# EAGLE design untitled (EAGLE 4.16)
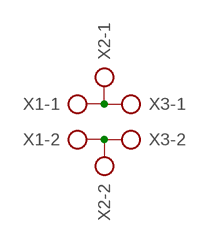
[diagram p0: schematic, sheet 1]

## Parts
X1  AK500/2  [AK500/2]
X2  AK500/2  [AK500/2]
X3  AK500/2  [AK500/2]

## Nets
N$17: X1.1 X2.1 X3.1
N$18: X1.2 X2.2 X3.2

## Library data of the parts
X1-X3 = con-ptr500:AK500/2: CONNECTOR

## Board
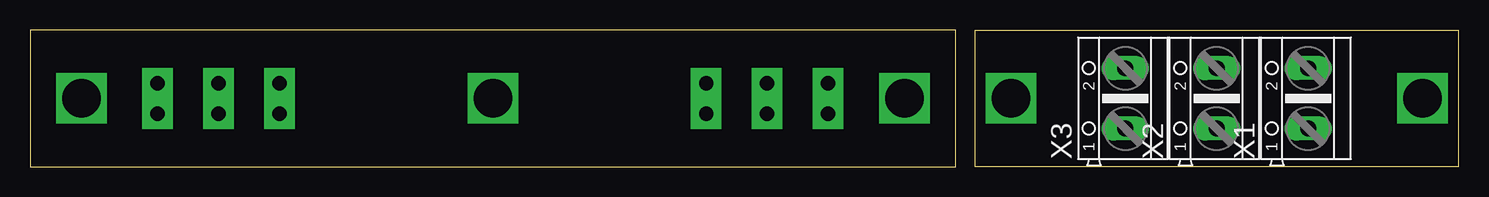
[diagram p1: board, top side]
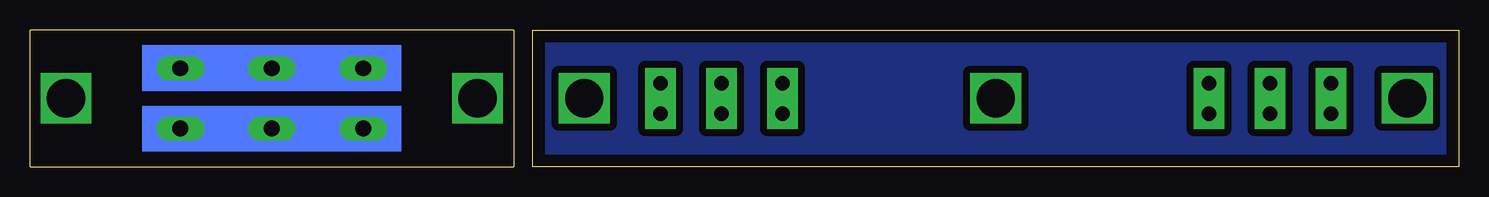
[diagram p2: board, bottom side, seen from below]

Size 119.05 x 11.44 mm. Coordinates in mm from the lower left corner, seen from the top.
Outline: 119.05,0.01 119.05,11.43
Outline: 78.74,11.43 78.74,0.01
Outline: 119.05,0 78.74,0
Outline: 78.74,11.44 119.05,11.44
Outline: 0,0.01 77.14,0.01 77.14,11.43 0,11.43 0,0.01
Copper layers (1*16): Top 0.035mm / dielectric 1.5mm / Bottom 0.035mm
Design rules "default": minimum track width 10mil, minimum drill 24mil, track to track 8mil, track to pad 8mil, pad to pad 8mil, via to via 8mil, smd to smd 8mil, copper to edge 40mil, drill to drill 8mil, minimum pad ring 10mil, minimum via ring 8mil, stop-mask expansion 4mil, vias tented up to drill 0mil, thermal gap 10mil

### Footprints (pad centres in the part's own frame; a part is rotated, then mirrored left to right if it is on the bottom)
AK500/2 = drill 1.321 long: 1 -2.515,0; 2 2.515,0

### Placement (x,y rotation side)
X1  106.52,5.72 90 top
X2  98.9,5.72 90 top
X3  91.28,5.72 90 top

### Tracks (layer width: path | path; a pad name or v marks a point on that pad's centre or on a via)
N$1  (via drill 1.2 pad 2.54)
  other vias: 20.79,6.99
N$2  (via drill 1.2 pad 2.54)
  other vias: 15.71,6.99
N$3  (via drill 1.2 pad 2.54)
  other vias: 10.63,6.99
N$4  (via drill 1.2 pad 2.54)
  other vias: 56.35,6.99
N$5  (via drill 1.2 pad 2.54)
  other vias: 61.43,6.99
N$6  (via drill 1.2 pad 2.54)
  other vias: 66.51,6.99
N$7  (via drill 3.2 pad 3.81)
  other vias: 4.28,5.72
N$8  (via drill 3.2 pad 3.81)
  other vias: 116.04,5.72
N$9  (via drill 3.2 pad 3.81)
  other vias: 38.57,5.72
N$10  (via drill 1.2 pad 2.54)
  other vias: 10.63,4.45
N$11  (via drill 1.2 pad 2.54)
  other vias: 15.71,4.45
N$12  (via drill 1.2 pad 2.54)
  other vias: 20.79,4.45
N$13  (via drill 1.2 pad 2.54)
  other vias: 56.35,4.45
N$14  (via drill 1.2 pad 2.54)
  other vias: 61.43,4.45
N$15  (via drill 1.2 pad 2.54)
  other vias: 66.51,4.45
N$16
  pour Bottom (isolate 0.61, no thermals): -0.8,12.07 77.94,12.07 77.94,-0.63 -0.8,-0.63
N$17
  Bottom 0.61: X2.1 X1.1 | X2.1 99.53,3.18 | X2.1 X3.1 90.64,3.18
N$18
  Bottom 0.61: X3.2 X2.2 | X2.2 99.53,8.26 | X2.2 X1.2 105.25,8.26
N$19  (via drill 3.2 pad 3.81)
  other vias: 72.86,5.72
N$20  (via drill 3.2 pad 3.81)
  other vias: 81.75,5.72
(copper drawn outside any net)
  shapes: Bottom area x2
